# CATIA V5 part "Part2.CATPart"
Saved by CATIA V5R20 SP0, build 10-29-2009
Part number: Part2
Bounding box of the stored display mesh (mm): x -12.5 to 12.5, y -12.31 to 12.31, z 0 to 170
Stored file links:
  C:\Users\YS\Desktop\독수리\Part2.CATPart
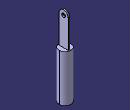
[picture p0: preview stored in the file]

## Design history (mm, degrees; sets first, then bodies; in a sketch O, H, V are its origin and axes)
Body1 (main body)
  Sketch1 on xy-plane, origin (0, 0, 0), H (1, 0, 0), V (0, 1, 0)
    circle A1 centre (0, 0) radius 12.5
    radius A1 = 12.5
  Pad1: profile Sketch1, direction (0, 0, 1), length 100
  Sketch2 on yz-plane, origin (0, 0, 0), H (0, 1, 0), V (0, 0, 1)
    line L1 (10, 160) -> (10, 100)
    line L2 (10, 100) -> (-10, 100)
    line L3 (-10, 100) -> (-10, 160)
    reference projected line E1 (-12.5, 100) -> (12.5, 100) from edge [face of Pad1 from Sketch1.A1 | end face of Pad1]
    arc A1 centre (0, 160) radius 10 from (10, 160) to (-10, 160) ccw
    distance L1 L3 = 20
    radius A1 = 10
    length L1 = 60
    horizontal: L2 H
    vertical: L1 V, L3 V
    coincidence: E1 L2
    symmetry: L1 L3 V
    tangency: A1 L1
  Pad2: profile Sketch2, direction (1, 0, 0), length 3
  Sketch3 on end face of Pad2, origin (3, 0, 0), H (0, 1, 0), V (0, 0, 1)
    circle A1 centre (0, 160) radius 4
    reference projected arc E1 centre (0, 160) radius 10 from (10, 160) to (-10, 160) ccw from edge [face of Pad2 from Sketch2.A1 | end face of Pad2]
    radius A1 = 4
    concentricity: E1 A1
  Pocket1: profile Sketch3, direction (-1, 0, 0), through (limit type 3)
